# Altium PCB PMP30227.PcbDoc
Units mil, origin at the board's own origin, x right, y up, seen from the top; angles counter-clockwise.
Board outline 3300 x 3700 mil, 2 copper layers (Top Layer, Bottom Layer), stack 62 mil thick; 42 components, 19 nets, 111 pads, 49 vias.
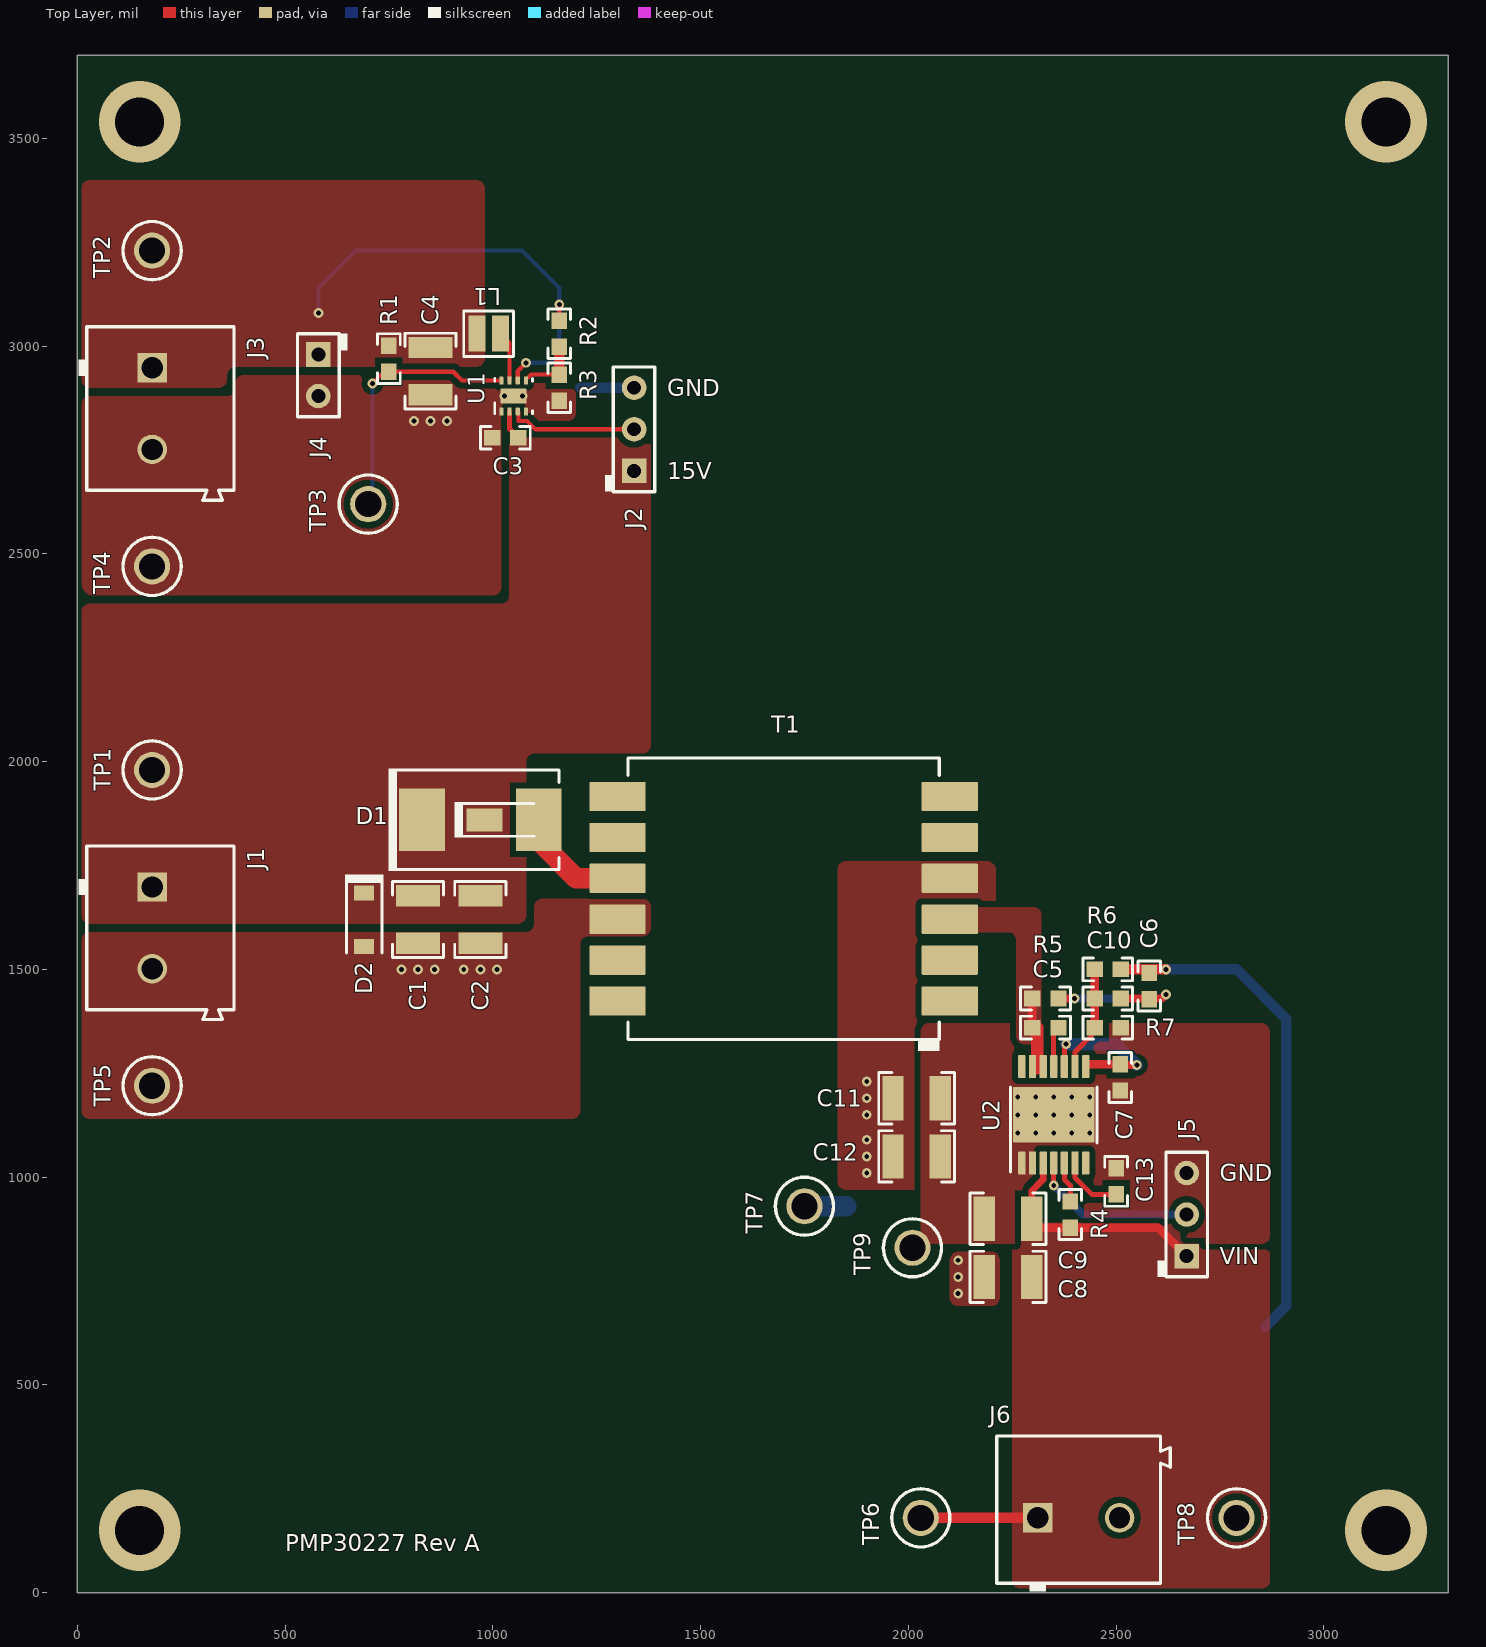
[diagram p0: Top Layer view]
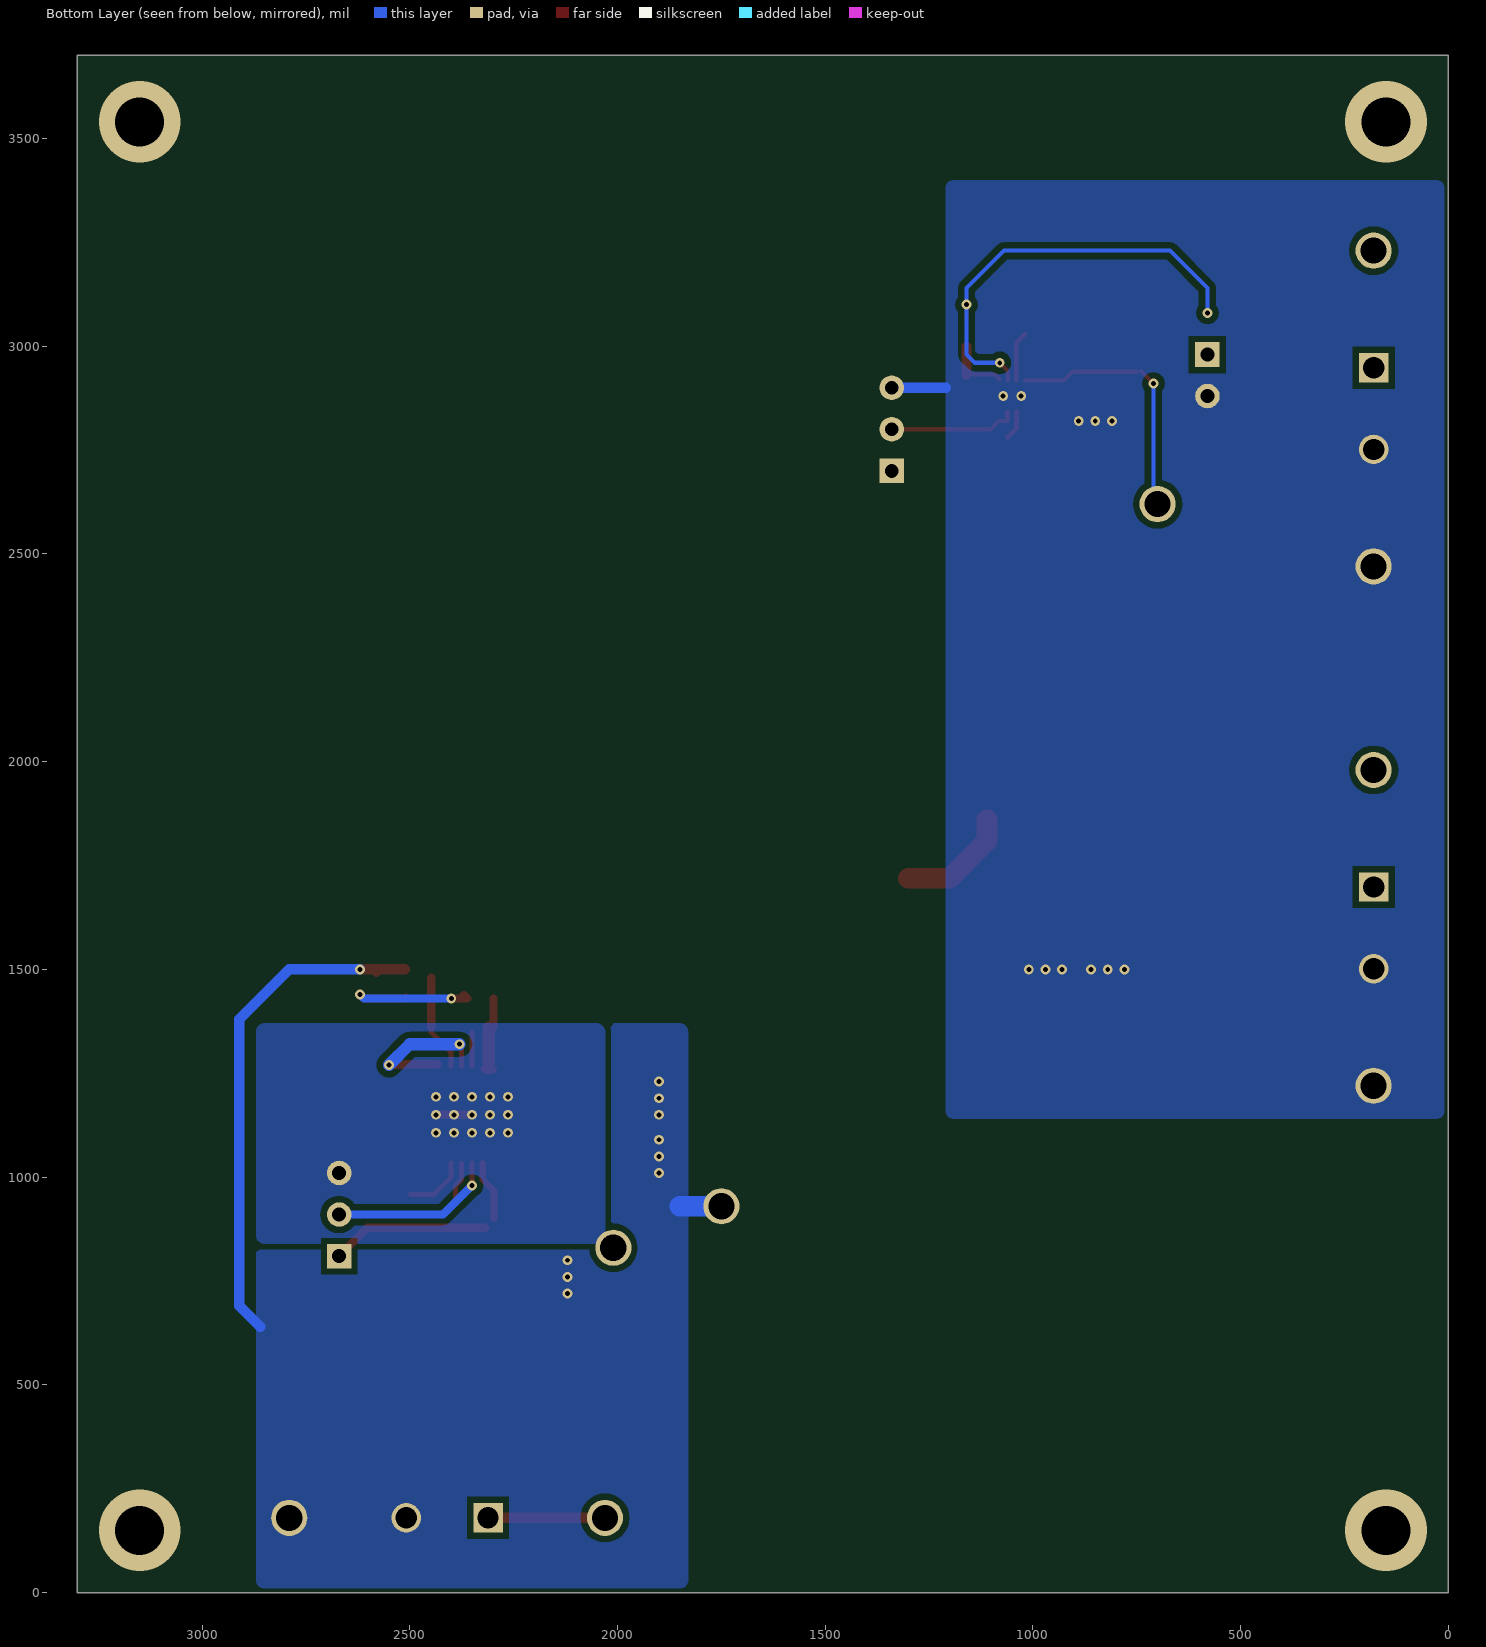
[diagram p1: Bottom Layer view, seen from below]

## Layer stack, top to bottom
Top Solder: solder mask 0.4, Solder Resist, Dk 3.5
Top Layer: signal copper 1.4
Dielectric1: core 59.2, FR-4, Dk 4.8
Bottom Layer: signal copper 1.4
Bottom Solder: solder mask 0.4, Solder Resist, Dk 3.5

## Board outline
0,0 3300,0 3300,3700 0,3700

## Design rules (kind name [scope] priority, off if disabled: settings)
AcuteAngle [All] p1: minimum=4.50000000000000E+0001 checktracksonly=FALSE
AssemblyTestPointUsage [All] p1: valid=2
Clearance Clearance_Keepouts [((IsTrack Or IsArc) And Not InPoly) And IsFree and IsKeepOut vs ((IsTrack Or IsArc) And Not InPoly) And IsFree and IsKeepOut] p1: gap=0
Clearance Clearance_BoardEdge_MountingHoles [OnCopper and InComponentClass('Mounting Holes') vs IsKeepOut] p2: gap=40
Clearance Clearance_BoardEdge_Poly [OnCopper and InPoly vs IsKeepOut] p3: gap=25
Clearance Clearance_BoardEdge [OnCopper and Not InComponentClass('Logo') and not InComponentClass('FiducialMark') and not InRegion(1000,500,4000,800) and Not IsKeepout vs IsKeepOut] p4: gap=75
Clearance Clearance_Poly [InPolygon] p5: gap=15
Clearance [All] p6: gap=7.87
ComponentClearance ComponentClearance_MountingHoles_FiducialMarks [InComponentClass('Mounting Holes') vs InComponentClass('FiducialMark')] p1: gap=50 collisioncheckmode=3 verticalgap=10 showdistances=FALSE
ComponentClearance ComponentClearance_Shunt [InComponentClass('Header') vs InComponentClass('Shunt')] p2: gap=0 collisioncheckmode=3 verticalgap=0 showdistances=FALSE
ComponentClearance ComponentClearance_Logo [InComponentClass('Logo')] p3: gap=50 collisioncheckmode=3 verticalgap=10 showdistances=FALSE
ComponentClearance ComponentClearance_ScrewToNut [(HasFootprint('NY PMS 440 0025 PH')) vs (HasFootprint('Keystone_1902C'))] p4: gap=5 collisioncheckmode=3 verticalgap=10 showdistances=FALSE
ComponentClearance ComponentClearance_MountingHoles [InComponentClass('Mounting Holes')] p5: gap=250 collisioncheckmode=3 verticalgap=100000 showdistances=FALSE
ComponentClearance ComponentClearance_SmallPassives [HasFootprint('0201*') or HasFootprint('0402*') or HasFootprint('0508') or HasFootprint('0603*') or HasFootprint('0612') or HasFootprint('0805*') or HasFootprint('0815*') or HasFootprint('0830*') or HasFootprint('1206*') or HasFootprint('1210*') or HasFootprint('1808*') or HasFootprint('1812*') or HasFootprint('1825*') or HasFootprint('2010*') or HasFootprint('2220*') or HasFootprint('2225*') or HasFootprint('2512*') or HasFootprint('2728*') or HasFootprint('3518*') vs HasFootprint('0201*') or HasFootprint('0402*') or HasFootprint('0508') or HasFootprint('0603*') or HasFootprint('0612') or HasFootprint('0805*') or HasFootprint('0815*') or HasFootprint('0830*') or HasFootprint('1206*') or HasFootprint('1210*') or HasFootprint('1808*') or HasFootprint('1812*') or HasFootprint('1825*') or HasFootprint('2010*') or HasFootprint('2220*') or HasFootprint('2225*') or HasFootprint('2512*') or HasFootprint('2728*') or HasFootprint('3518*')] p6: gap=20 collisioncheckmode=3 verticalgap=10 showdistances=FALSE
ComponentClearance ComponentClearance_THtoSMT [IsThruComponent vs IsSMTComponent] p7: gap=100 collisioncheckmode=3 verticalgap=30 showdistances=FALSE
ComponentClearance ComponentClearance_THtoTH [IsThruComponent vs IsThruComponent] p8: gap=118.11 collisioncheckmode=3 verticalgap=30 showdistances=FALSE
ComponentClearance [All] p9: gap=40 collisioncheckmode=3 verticalgap=10 showdistances=FALSE
DiffPairsRouting [All] p1: maxlimit=100 minlimit=10 mostfreqgap=10 toplayer_minwidth=15 toplayer_maxwidth=15 toplayer_prefwidth=15 bottomlayer_minwidth=15 bottomlayer_maxwidth=15 bottomlayer_prefwidth=15 maxuncoupledlength=1000
FabricationTestPointUsage TestPointUsage [All] p1: valid=2 allowmultiple=FALSE
FabricationTestpoint Testpoint [All] p1: side=3 testpointundercomponent=TRUE minsize=40 maxsize=100 preferedsize=60 minholesize=0 maxholesize=40 preferedholesize=32 testpointgrid=1 allowsidetop=TRUE allowsidebottom=TRUE usegrid=TRUE gridtolerance=0.01
FanoutControl Fanout_LCC [IsLCC] p1: bgadir=Out bgaviamode=Centered fanoutstyle=Auto fanoutdirection=Alternating viagrid=1 // Fanout_LCC (Default Rule)
FanoutControl Fanout_BGA [IsBGA] p2: bgadir=Out bgaviamode=Centered fanoutstyle=Auto fanoutdirection=Alternating viagrid=1 // Fanout_BGA (Default Rule)
FanoutControl Fanout_Default [All] p4: bgadir=Out bgaviamode=Centered fanoutstyle=Auto fanoutdirection=Alternating viagrid=1 // Fanout_Default (Default Rule)
FanoutControl Fanout_Small [(CompPinCount < 5)] p5: bgadir=Out bgaviamode=Centered fanoutstyle=Auto fanoutdirection=OutThenIn viagrid=1 // Fanout_Small (Default Rule)
HoleSize [All] p1: absolutevalues=TRUE maxlimit=251 minlimit=8 maxpercent=80.000 minpercent=20.000
MinimumAnnularRing MinimumAnnularRing_ThermalPadVias [IsVia and InAnyComponent] p1: minimumring=5.91
MinimumAnnularRing [All] p2: minimumring=9
MinimumSolderMaskSliver MinimumSolderMaskSliver_Logo [InComponentClass('Logo') vs InComponentClass('Logo')] p1: minsoldermaskwidth=0.7
MinimumSolderMaskSliver [All] p2: minsoldermaskwidth=3.94
PlaneConnect [All] p1: planeconnectstyle=Relief reliefexpansion=10 reliefentries=4 reliefconductorwidth=10 reliefairgap=10
PolygonConnect [All] p1: connectstyle=Direct reliefconductorwidth=10 reliefentries=4 polygonreliefangle="90 Angle" airgapwidth=10
RoutingVias ThermalPadVias [IsVia and InAnyComponent] p1: holewidth=7.87 width=19.68 viastyle="Through Hole" minholewidth=7.87 minwidth=19.68 maxholewidth=12.99 maxwidth=23.62
RoutingVias [All] p2: holewidth=16 width=34 viastyle="Through Hole" minholewidth=7.87 minwidth=26 maxholewidth=40 maxwidth=65
SilkToBoardRegionClearance [Not ((IsComment or IsDesignator) And (Hide <> 'False')) and not InRegion(1000,500,4000,800)] p1:
SilkToSilkClearance SilkToSilkClearance_Pb-FreeLogo [(HasFootprint('Pb-Free_Overlay_Medium') OR HasFootprint('Pb-Free_Overlay_Small')) vs (HasFootprint('Pb-Free_Overlay_Medium') OR HasFootprint('Pb-Free_Overlay_Small'))] p1: silktosilkclearance=0
SilkToSilkClearance [All] p2: silktosilkclearance=4
SilkToSolderMaskClearance SilkToComonentPadClearance [IsPad and InAnycomponent] p1: minsilkscreentomaskgap=5 clearancetoexposedcopper=TRUE
SilkToSolderMaskClearance "Silk to Solder Mask Opening" [All] p2: minsilkscreentomaskgap=4 clearancetoexposedcopper=FALSE
SolderMaskExpansion [All] p1: expansion=1.97
Width [All] p1: maxlimit=100 minlimit=6 preferedwidth=10 checkconnectedcopper=TRUE
15 further rules are at their usual default settings.

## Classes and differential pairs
component class Header: J2 J4 J5

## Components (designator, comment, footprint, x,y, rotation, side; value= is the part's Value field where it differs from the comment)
C1 "GRM32DR71E106KA12L" 1210_220 820,1620 r270 top
C2 "GRM32DR71E106KA12L" 1210_220 970,1620 r270 top
C3 "GRM188R71E104KA01D" 0603 1030,2780 r180 top
C4 "GRM32ER71A226ME20L" 1210_270 850,2940 r270 top
C5 "GRM188R71C103KA01D" 0603 2330,1360 r0 top
C6 "GRM188R71H103KA01D" 0603 2580,1460 r270 top
C7 "GRM188R71C105KA12D" 0603 2510,1240 r90 top
C8 "GRM32ER71H475KA88L" 1210_270 2240,760 r180 top
C9 "GRM32ER71H475KA88L" 1210_270 2240,900 r180 top
C10 "GRM188R72A102KA01D" 0603 2480,1430 r180 top
C11 "GRM32DR71E106KA12L" 1210_220 2020,1190 r0 top
C12 "GRM32DR71E106KA12L" 1210_220 2020,1050 r0 top
C13 "GRM188R71C104KA01D" 0603 2500,990 r90 top
D1 "DFLS1100-7" PowerDI123 1030,1860 r0 top
D1 "=PartNumber" SMC 970,1860 r0 top
D2 "MMSZ5246B-7-F" SOD-123 690.32,1620 r270 top
J1 "691 101 710 002" Wurth_691101710002 180,1600 r270 top
J2 "800-10-003-10-001000" Mill-Max_800-10-003-10-001000 1340,2800 r90 top
J3 "691 101 710 002" Wurth_691101710002 180,2850 r270 top
J4 "800-10-002-10-001000" Mill-Max_800-10-002-10-001000 580,2930 r270 top
J5 "800-10-003-10-001000" Mill-Max_800-10-003-10-001000 2670,910 r90 top
J6 "691 101 710 002" Wurth_691101710002 2410,180 r0 top
L1 "XPL2010-222MLB" XPL2010 990,3030 r180 top
R1 "CRCW0603100KFKEA" 0603 750,2970 r90 top
R2 "CRCW060368K0JNEA" 0603 1160,3030 r90 top
R3 "CRCW060313K0FKEA" 0603 1160,2900 r90 top
R4 "CRCW0603174KFKEA" 0603 2390,910 r90 top
R5 "CRCW060310K0FKEA" 0603 2330,1430 r0 top
R6 "CRCW0603100KFKEA" 0603 2480,1500 r0 top
R7 "CRCW060335K7FKEA" 0603 2480,1360 r180 top
T1 "WA8417-AL" Coilcraft_WA8417-AL 1700,1670 r180 top
TP1 "5010" Keystone5010 180,1980 r270 top
TP2 "5010" Keystone5010 180,3230 r90 top
TP3 "5012" Keystone5012 700,2620 r90 top
TP4 "5011" Keystone5011 180,2470 r90 top
TP5 "5011" Keystone5011 180,1220 r270 top
TP6 "5010" Keystone5010 2030,180 r90 top
TP7 "5011" Keystone5011 1750,930 r90 top
TP8 "5011" Keystone5011 2790,180 r90 top
TP9 "5010" Keystone5010 2010,830 r90 top
U1 "TPS62170QDSGRQ1" DSG0008A 1050,2880 r90 top
U2 "LM5160QPWPRQ1" PWP0014A_N 2350,1150 r90 top

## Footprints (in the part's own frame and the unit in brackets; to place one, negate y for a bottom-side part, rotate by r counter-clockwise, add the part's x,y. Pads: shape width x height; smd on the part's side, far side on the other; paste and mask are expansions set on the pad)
0603 [mm] "0603 from SM-752 data"
  rect 1x0.95 smd: 1(-0.8,0) 2(0.8,0)
  silkscreen extent -1.52,-0.69 1.52,0.69, body extent -0.87,-0.47 0.87,0.47, height 1
1210_220 [mm] "1210"
  rect 1.3x2.7 smd: 1(-1.45,0) 2(1.45,0)
  silkscreen extent -2.32,-1.57 2.32,1.57, body extent -1.7,-1.35 1.7,1.35, height 2.2
1210_270 [mm] "1210"
  rect 1.3x2.7 smd: 1(-1.45,0) 2(1.45,0)
  silkscreen extent -2.32,-1.57 2.32,1.57, body extent -1.7,-1.35 1.7,1.35, height 2.7
Coilcraft_WA8417-AL [mm] "SMD, 12-Leads, Body 22x17.2mm, Pitch 2.5mm"
  rrect6% 3.43x1.79 smd: 1(-10.155,6.25) 2(-10.155,3.75) 3(-10.155,1.25) 4(-10.155,-1.25) 5(-10.155,-3.75) 6(-10.155,-6.25) 7(10.155,-6.25) 8(10.155,-3.75) 9(10.155,-1.25) 10(10.155,1.25) 11(10.155,3.75) 12(10.155,6.25)
  silkscreen extent -9.52,-8.6 9.52,9.3, body extent -11,-8.6 11,8.6, height 8.64
DSG0008A [mm] "SON, 8-Leads, Body 2x2mm, Pitch 0.5mm, Thermal Pad 1.6x0.9mm, TI Recommended"
  rrect40% 0.5x0.25 smd: 1(-0.95,0.75) 2(-0.95,0.25) 3(-0.95,-0.25) 4(-0.95,-0.75) 5(0.95,-0.75) 6(0.95,-0.25) 7(0.95,0.25) 8(0.95,0.75)
  rrect14% 0.9x0.7 on Top Paste: 9(0,0.45) 9(0,-0.45)
  rrect11% 0.9x1.6 smd paste-0.45: 9(0,0)
  silkscreen extent -1.07,-1.15 1.07,1.15, body extent -1,-1 1,1, height 0.77
Keystone5010 [mil] "Keystone Multipurpose loops"
  round 87 hole 63: 1(0,0)
  silkscreen extent -70,-70 70,70, body extent -63,-63 63,62, height 319
Keystone5011 [mil] "Keystone Multipurpose loops"
  round 87 hole 63: 1(0,0)
  silkscreen extent -70,-70 70,70, body extent -63,-63 63,62, height 319
Keystone5012 [mil] "Keystone Multipurpose loops"
  round 87 hole 63: 1(0,0)
  silkscreen extent -70,-70 70,70, body extent -63,-63 63,62, height 319
Mill-Max_800-10-002-10-001000 [mm] "Mill-Max"
  rect 1.5x1.5 hole 0.85: 1(-1.27,0)
  round 1.5 hole 0.85: 2(1.27,0)
  silkscreen extent -2.54,-1.27 2.54,1.78, body extent -2.54,-1.27 2.54,1.27, height 8.13
Mill-Max_800-10-003-10-001000 [mm] "Mill-Max"
  rect 1.5x1.5 hole 0.85: 1(-2.54,0)
  round 1.5 hole 0.85: 2(0,0) 3(2.54,0)
  silkscreen extent -3.81,-1.27 3.81,1.78, body extent -3.81,-1.27 3.81,1.27, height 8.13
PowerDI123 [mm] "Diodes Inc recommended land pattern, document number DS30628 Rev. 6-2"
  rect 2.2x1.4 smd: 1(-1.275,0)
  rect 0.9x1.4 smd: 2(1.275,0)
  silkscreen extent -3.1,-1.09 1.76,1.09, body extent -2.38,-0.97 1.52,0.96, height 1
PWP0014A_N [mm] "TSOP, 14-Leads, Body 5x4.4mm, Pitch 0.65mm, Thermal Pad 3x3.1 mm, IPC Medium Density"
  rrect22% 1.4x0.45 smd: 1(-2.95,1.95) 2(-2.95,1.3) 3(-2.95,0.65) 4(-2.95,0) 5(-2.95,-0.65) 6(-2.95,-1.3) 7(-2.95,-1.95) 8(2.95,-1.95) 9(2.95,-1.3) 10(2.95,-0.65) 11(2.95,0) 12(2.95,0.65) 13(2.95,1.3) 14(2.95,1.95)
  rrect6% 3.4x5 smd paste-2 mask-2: 15(0,0)
  rrect3% 3.155x3.255 on Top Paste: 15(0,0)
  rrect3% 3.155x3.255 on Top Solder: 15(0,0)
  silkscreen extent -3.47,-2.65 1.7,2.65, body extent -3.21,-2.5 3.21,2.5, height 1
SMC [mil] "Molded Diode, 2-Leads, Body 6.9x5.8mm, IPC Medium Density, based on OnSemi component dimensions and land patterns"
  rect 110x150 smd: 1(-140.49,0) 2(140.49,0)
  silkscreen extent -221,-124 189,124, body extent -156,-116 156,116, height 91
SOD-123 [mm] "On Semi recommended land pattern"
  rect 0.915x1.22 smd: 1(-1.637,0) 2(1.637,0)
  silkscreen extent -2.74,-1.17 2.03,1.17, body extent -1.93,-0.9 1.93,0.9, height 1.35
Wurth_691101710002 [mm] "Terminal Block, 5 mm, 2x1, TH"
  rect 1.8x1.8 hole 1.3: 1(-2.5,0)
  round 1.8 hole 1.3: 2(2.5,0)
  silkscreen extent -5,-4.5 5.6,5, body extent -5.6,-4 5.6,5, height 12.5
XPL2010 [mm] "Coilcraft recommended land pattern Document 646-2 Revised 3/28/11"
  rect 1.04x2.2 smd: 1(-0.725,0) 2(0.725,0)
  silkscreen extent -1.52,-1.4 1.52,1.4, body extent -1.05,-1.1 1.05,1.1, height 1

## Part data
C1 C2 C11 C12: "CAP, CERM, 10 µF, 25 V, +/- 10%, X7R, 1210"
C3: "CAP, CERM, 0.1 µF, 25 V, +/- 10%, X7R, 0603"
C4: "CAP, CERM, 22 µF, 10 V, +/- 10%, X7R, 1210"
C5: "CAP, CERM, 0.01 µF, 16 V, +/- 10%, X7R, 0603"
C6: "CAP, CERM, 0.01 µF, 50 V, +/- 10%, X7R, 0603"
C7: "CAP, CERM, 1 µF, 16 V, +/- 10%, X7R, 0603"
C8 C9: "CAP, CERM, 4.7 µF, 50 V, +/- 10%, X7R, 1210"
C10: "CAP, CERM, 1000 pF, 100 V, +/- 10%, X7R, 0603"
C13: "CAP, CERM, 0.1 µF, 16 V, +/- 10%, X7R, 0603"
D1: "Diode, Schottky, 100 V, 1 A, PowerDI123"
D1: library part VS-30BQ100TRPBF, "Diode, Schottky, 100 V, 3 A, SMC"
D2: "Diode, Zener, 16 V, 500 mW, SOD-123"
J1 J3 J6: "Terminal Block, 5 mm, 2x1, Tin, TH"
J2 J5: "Header, 100mil, 3x1, TH"
J4: "Header, 100mil, 2x1, TH"
L1: "Inductor, Shielded, Composite, 2.2 µH, 1.3 A, 0.16 ohm, SMD"
R1 R6: "RES, 100 k, 1%, 0.1 W, 0603"
R2: "RES, 68 k, 5%, 0.1 W, 0603"
R3: "RES, 13.0 k, 1%, 0.1 W, 0603"
R4: "RES, 174 k, 1%, 0.1 W, 0603"
R5: "RES, 10.0 k, 1%, 0.1 W, 0603"
R7: "RES, 35.7 k, 1%, 0.1 W, 0603"
T1: "Transformer, 47 uH, SMT"
TP1 TP2 TP6 TP9: "Test Point, Multipurpose, Red, TH"
TP3: "Test Point, Multipurpose, White, TH"
TP4 TP5 TP7 TP8: "Test Point, Multipurpose, Black, TH"
U1: "3-17V 0.5A Automotive Step-Down Converter in 2x2 QFN package, DSG0008A (WSON-8)"
U2: "Wide Input 65V, 1.5A Synchronous Buck / Fly-Buck(TM) Converter, PWP0014A (TSSOP-14)"

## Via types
v1: diameter 23.62, hole 11.81, Top Layer to Bottom Layer, 39 vias
v2: diameter 23.62, hole 11.81, Top Layer to Bottom Layer, tented both sides, 6 vias
v3: diameter 196.85, hole 118.11, Top Layer to Bottom Layer, 4 vias

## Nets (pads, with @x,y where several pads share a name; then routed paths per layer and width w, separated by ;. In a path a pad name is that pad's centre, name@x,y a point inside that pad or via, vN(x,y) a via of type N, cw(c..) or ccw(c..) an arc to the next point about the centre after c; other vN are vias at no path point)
15V: C1.1 C2.1 C3.1 D1.1 D2.1 J1.1 J2.1 TP1.1 U1.2 | length 72.9
  Top Layer w10: C3.1@1060,2780 C3.1
  Top Layer w12: U1.2 1040.16,2801.34 C3.1
GND: C6.1 C8.2 C11.1 C12.1 J6.2 R6.2 T1.4 TP7.1 TP8.1 | length 1320.9
  Top Layer w20: C6.1 C6.1@2588.5,1500
  Top Layer w25: R6.2 v1(2620,1500)
  Bottom Layer w25: v1(2620,1500) 2790,1500 2910,1380 2910,690 2860,640
  Bottom Layer w50: TP7.1 1850,930
  other v1: 2120,720 2120,760 2120,800 1900,1010 1900,1050 1900,1090 1900,1150 1900,1190 1900,1230
ISOGND: C1.2 C2.2 C3.2 C4.2 D2.2 J1.2 J2.3 J3.2 J4.2 R3.1 T1.10 TP4.1 TP5.1 U1.1 U1.4 U1.9@1050,2880 | length 131.7
  Bottom Layer w12: v1@1070,2880 v1(1071.65,2880)
  Bottom Layer w25: 1210,2900 J2.3
  other v1: 780,1500 820,1500 860,1500 930,1500 970,1500 1010,1500 810,2820 850,2820 890,2820 1028.35,2880
NetC4_1: C4.1 J3.1 J4.1 L1.2 R1.2 R2.2 TP2.1 U1.6 | length 1052.5
  Top Layer w10: U1.6@1060,2917.56 U1.6 1059.84,2939.84 v1(1080,2960) ; R2.2 v1(1160,3100)
  Bottom Layer w10: v1(580,3080) 580,3140 670,3230 1070,3230 1160,3140 v1(1160,3100) 1160,2980 1140,2960 v1(1080,2960)
NetC5_1: C5.1 R5.1 T1.3 U2.12 U2.13 | length 190.6
  Top Layer w20: R5.1 C5.1 C5.1@2299.96,1358.54 ; U2.13@2299.96,1260.04 U2.12@2319.96,1260.04
  Top Layer w30: 2310,1261.5 C5.1@2310,1360
NetC5_2: C5.2 U2.11 | length 82.4
  Top Layer w12: U2.11 C5.2@2350,1348.5
NetC6_2: C6.2 C10.1 R5.2 | length 389.4
  Top Layer w20: R5.2@2370,1438.5 R5.2 v1(2400,1430) ; C10.1@2510,1431.5 C10.1 2610,1430 v1(2620,1440)
  Bottom Layer w20: v1(2400,1430) 2610,1430 v1(2620,1440)
NetC7_1: C7.1 C9.2 C11.2 C12.2 C13.2 J5.3 R7.1 TP9.1 U2.1 U2.2 U2.15@2350,1150 | length 86.6
  Top Layer w20: v1(2350,1150) v1(2393.31,1150) v2(2436.61,1150)
  other v1: 2306.69,1106.69 2350,1106.69 2393.31,1106.69 2306.69,1150 2306.69,1193.31 2350,1193.31 2393.31,1193.31
  other v2: 2263.39,1106.69 2436.61,1106.69 2263.39,1150 2263.39,1193.31 2436.61,1193.31
NetC7_2: C7.2 U2.8 U2.10 | length 361.6
  Top Layer w12: U2.10 2375.59,1315.59 v1(2380,1320)
  Top Layer w20: U2.8@2433.27,1271.5 C7.2 ; C7.2@2511.5,1270 v1(2550,1270)
  Bottom Layer w29.53: v1(2380,1320) 2500,1320 v1(2550,1270)
NetC8_1: C8.1 C9.1 J5.1 J6.1 R4.1 TP6.1 U2.3 | length 805
  Top Layer w16: C9.1 2297.09,967.09 2324.41,994.41 U2.3
  Top Layer w20: C9.1@2318.58,878.5 R4.1 2601.5,878.5 J5.1
  Top Layer w25: TP6.1 J6.1@2310,180
NetC10_2: C10.2 R6.1 R7.2 U2.9 | length 222
  Top Layer w12: U2.9 2401.18,1301.18 R7.2@2448.5,1348.5
  Top Layer w20: R7.2 C10.2 2448.5,1480
NetC13_1: C13.1 U2.6 | length 150.6
  Top Layer w12: U2.6 2401.18,998.82 2441.5,958.5 C13.1
NetD1_2: D1.2 T1.9 | length 277.6
  Top Layer w50: D1.2@1110.49,1860 1110.49,1809.51 1200.79,1719.21 T1.9
NetJ2_2: J2.2 U1.3 | length 309.9
  Top Layer w10: U1.3 1061.73,2840.71 1061.73,2820.03 1061.88,2819.88 1082.56,2819.88 1102.44,2800 J2.2
NetJ5_2: J5.2 U2.4 | length 402.9
  Top Layer w12: v1(2350,980) U2.4
  Bottom Layer w19.68: v1(2350,980) 2420,910 J5.2
NetL1_1: L1.1 U1.7 | length 121.6
  Top Layer w10: L1.1 1040.16,3008.39 U1.7
NetR1_1: R1.1 TP3.1 U1.8 | length 619.9
  Top Layer w10: v1(710,2910) R1.1@740,2940 ; R1.1 904.65,2938.5 925.75,2917.4 U1.8
  Bottom Layer w10: TP3.1@690,2620 710,2640 v1(710,2910)
NetR2_1: R2.1 R3.2 U1.5 | length 151.8
  Top Layer w10: U1.5@1080,2920 1091.5,2931.5 R3.2
  Top Layer w25: R3.2 R2.1
NetR4_2: R4.2 U2.5 | length 98.3
  Top Layer w12: U2.5 2375.59,994.41 2390,980 R4.2
pads on no net: T1.1 T1.2 T1.5 T1.6 T1.7 T1.8 T1.11 T1.12 U1.9@1032.28,2880 U1.9@1067.72,2880 U2.7 U2.14 U2.15@2350,1150
copper on no net:
  other v3: 150,150 3150,150 150,3540 3150,3540

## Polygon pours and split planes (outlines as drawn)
GND on Top Layer "Top Layer-No Net 8" (solid, remove dead copper, pour order 28): 2100,800 cw(c2120,800) 2120,820 2200,820 cw(c2200,800) 2220,800 2220,710 cw(c2200,710) 2200,690 2120,690 cw(c2120,710) 2100,710
NetC4_1 on Top Layer "Top Layer-No Net" (solid, remove dead copper, pour order 0): 980,3000 980,2980 980,2970 cw(c960,2970) 960,2950 380,2950 ccw(c380,2930) 360,2930 360,2920 cw(c340,2920) 340,2900 30,2900 cw(c30,2920) 10,2920 10,3380 cw(c30,3380) 30,3400 960,3400 cw(c960,3380) 980,3380 980,3000
NetC5_1 on Top Layer "Top Layer-No Net 1" (solid, remove dead copper, pour order 4): 2160,1590 2220,1590 2240,1590 cw(c2240,1570) 2260,1570 2260,1340 ccw(c2280,1340) 2280,1320 2300,1320 ccw(c2300,1340) 2320,1340 2320,1630 ccw(c2300,1630) 2300,1650 2160,1650
ISOGND on Top Layer "Top Layer-No Net 2" (solid, remove dead copper, pour order 6): 10,1470 10,1160 ccw(c30,1160) 30,1140 1190,1140 ccw(c1190,1160) 1210,1160 1210,1560 cw(c1230,1560) 1230,1580 1360,1580 ccw(c1360,1600) 1380,1600 1380,1650 ccw(c1360,1650) 1360,1670 1120,1670 ccw(c1120,1650) 1100,1650 1100,1610 cw(c1080,1610) 1080,1590 30,1590 ccw(c30,1570) 10,1570 10,1470
ISOGND on Top Layer "Top Layer-No Net 3" (solid, remove dead copper, pour order 8): 10,2850 10,2860 cw(c30,2860) 30,2880 360,2880 ccw(c360,2900) 380,2900 380,2910 cw(c400,2910) 400,2930 1180,2930 cw(c1180,2910) 1200,2910 1200,2840 cw(c1180,2840) 1180,2820 1040,2820 ccw(c1040,2800) 1020,2800 1020,2420 cw(c1000,2420) 1000,2400 40,2400 cw(c40,2430) 10,2430
15V on Top Layer "Top Layer-No Net 4" (solid, remove dead copper, pour order 10): 10,1630 ccw(c30,1630) 30,1610 1060,1610 ccw(c1060,1630) 1080,1630 1080,2000 cw(c1100,2000) 1100,2020 1360,2020 ccw(c1360,2040) 1380,2040 1380,2760 ccw(c1360,2760) 1360,2780 1060,2780 ccw(c1060,2760) 1040,2760 1040,2400 cw(c1020,2400) 1020,2380 30,2380 ccw(c30,2360) 10,2360
NetC7_1 on Top Layer "Top Layer-No Net 5" (solid, remove dead copper, pour order 14): 2030,1240 2030,1310 2030,1350 cw(c2050,1350) 2050,1370 2850,1370 cw(c2850,1350) 2870,1350 2870,1110 2870,860 cw(c2850,860) 2850,840 2050,840 cw(c2050,860) 2030,860 2030,1350
GND on Top Layer "Top Layer-No Net 6" (solid, remove dead copper, pour order 18): 2210,990 cw(c2190,990) 2190,970 1850,970 cw(c1850,990) 1830,990 1830,1740 cw(c1850,1740) 1850,1760 2190,1760 cw(c2190,1740) 2210,1740
NetC8_1 on Top Layer "Top Layer-No Net 7" (solid, remove dead copper, pour order 20): 2250,30 ccw(c2270,30) 2270,10 2850,10 ccw(c2850,30) 2870,30 2870,450 2870,870 ccw(c2850,870) 2850,890 2280,890 ccw(c2275,865) 2250,870
ISOGND on Bottom Layer "Bottom Layer-No Net" (solid, remove dead copper, pour order 26): 10,3380 10,1160 ccw(c30,1160) 30,1140 40,1140 1190,1140 ccw(c1190,1160) 1210,1160 1210,3380 ccw(c1190,3380) 1190,3400 30,3400 ccw(c30,3380) 10,3380
NetC7_1 on Bottom Layer "Bottom Layer-No Net 1" (solid, remove dead copper, pour order 16): 2030,1350 2030,1340 2030,860 ccw(c2050,860) 2050,840 2850,840 ccw(c2850,860) 2870,860 2870,1350 ccw(c2850,1350) 2850,1370 2050,1370 ccw(c2050,1350)
GND on Bottom Layer "Bottom Layer-No Net 2" (solid, remove dead copper, pour order 22): 1830,30 ccw(c1850,30) 1850,10 2850,10 ccw(c2850,30) 2870,30 2870,1350 ccw(c2850,1350) 2850,1370 1850,1370 ccw(c1850,1350) 1830,1350

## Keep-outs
Keep-Out Layer:
  lines w10: 4950,-5 ccw(c4950,0) 4955,0 cw(c4950,0) 4950,-5
  text ".Layer_Name" at 577,-858.49 h60

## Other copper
Top Layer:
  text ".Layer_Name" at 577,-858.49 h60
Bottom Layer:
  text ".Layer_Name" at 577,-858.49 h60

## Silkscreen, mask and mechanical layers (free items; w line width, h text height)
Top Overlay:
  text "GND" at 1420,2880 h40
  text "15V" at 1420,2680 h40
  text "GND" at 2750,990 h40
  text "VIN" at 2750,790 h40
  text "PMP30227 Rev A" at 500,100 h40
  text ".Layer_Name" at 577,-858.49 h60
Bottom Overlay:
  text ".Layer_Name" at 577,-858.49 h60
Top Paste:
  text ".Layer_Name" at 577,-858.49 h60
Bottom Paste:
  text ".Layer_Name" at 577,-858.49 h60
Top Solder:
  text "5V" at 280,3210 h40
  text "ISOGND" at 280,2460 h40
  text "15V" at 280,1960 h40
  text "ISOGND" at 280,1210 h40
  text "VIN" at 1980,320 h40
  text "GND" at 2730,320 h40
  text ".Layer_Name" at 577,-858.49 h60
  text ".Layer_Name" at 577,-858.49 h60
Bottom Solder:
  text ".Layer_Name" at 577,-858.49 h60
Drill Guide:
  text ".Layer_Name" at 577,-858.49 h60
M1 Board Outline:
  text ".Layer_Name" at 577,-858.49 h60
M2 Board Dimensions:
  rectangle: 0,-275 125,-150
  rectangle: 125,-400 500,-275
  lines w7: 0,-275 1000,-275 ; 125,-400 125,-150 ; 250,-400 250,-150 ; 500,-400 500,-150 ; 750,-400 750,-150 ; 0,-400 1000,-400 1000,-150 0,-150 0,-400
  text ".Layer_Name" at 577,-858.49 h60
M3 3D STEP Top:
  text ".Layer_Name" at 577,-858.49 h60
M4 3D STEP Bottom:
  text ".Layer_Name" at 577,-858.49 h60
M5 Assembly Top:
  lines w10: -292,-930.17 6308,-930.17 ; -292,-726.83 6310,-726.83 ; -292,-523.5 -292,-1133.5 3713,-1133.5 6310,-1133.5 6310,-523.5 -291.5,-523.5 -291.5,-1133.5 1284,-1133.5 ; 2173,-1133.5 2173,-523.5 ; 3440,-726.83 3440,-523.5 ; 4280,-726.83 4280,-523.5 ; 4902,-1140 4902,-937.17
  text "COMPONENTS MARKED 'DNP' SHOULD NOT BE POPULATED." at 1153.5,-318.5 h60
  text "ASSEMBLY VARIANT:" at 1153,-434 h60
  text ".VariantName" at 2189,-434 h60
  text "PCB VIEWED FROM TOP SIDE" at -228.5,-655.67 h60
  text "BOARD #:" at 2248,-655.67 h60
  text ".PRJ_Number" at 2793.5,-655.67 h60
  text "REV:" at 3638,-655.67 h60
  text ".PCB_Rev" at 3929.5,-655.67 h60
  text "SVN REV:" at 4476,-655.67 h60
  text ".VersionControl_RevNumber" at 4982,-655.67 h60
  text "TID #:" at 2248,-859 h60
  text ".TID" at 2793.5,-859 h60
  text "PLOT NAME =" at -228.5,-1064.34 h60
  text ".plot_File_Name" at 577,-1064.34 h60
  text "GENERATED    :" at 2250,-1064.34 h60
  text ".Print_Date" at 3119.5,-1064.34 h60
  text ".Print_Time" at 3848.5,-1064.34 h60
  text "TEXAS INSTRUMENTS" at 5113,-1064.34 h60
M6 Assembly Bottom:
  lines w10: -292.5,-727.33 6309.5,-727.33 ; -290.5,-930.67 6309.5,-930.67 ; 1115.5,-1140.5 1115.5,-937.67 ; 1737.5,-727.33 1737.5,-524 ; 2577.5,-727.33 2577.5,-524 ; 3844.5,-1134 3844.5,-524 ; 4733.5,-1134 6309,-1134 6309,-524 -292.5,-524 -292.5,-1134 2304.5,-1134 6309.5,-1134 6309.5,-524
  text "COMPONENTS MARKED 'DNP' SHOULD NOT BE POPULATED." at 6102,-318 h60
  text ".VariantName" at 5058,-434 h60
  text "ASSEMBLY VARIANT:" at 6097,-434 h60
  text ".VersionControl_RevNumber" at 1035.5,-656.17 h60
  text "SVN REV:" at 1541.5,-656.17 h60
  text ".PCB_Rev" at 2088,-656.17 h60
  text "REV:" at 2379.5,-656.17 h60
  text ".PRJ_Number" at 3224,-656.17 h60
  text "BOARD #:" at 3769.5,-656.17 h60
  text "PCB VIEWED FROM BOTTOM SIDE" at 6246,-656.17 h60
  text ".TID" at 3224,-859.5 h60
  text "TID #:" at 3769.5,-859.5 h60
  text "TEXAS INSTRUMENTS" at 904.5,-1064.84 h60
  text ".Print_Time" at 2169,-1064.84 h60
  text ".Print_Date" at 2898,-1064.84 h60
  text "GENERATED    :" at 3767.5,-1064.84 h60
  text ".plot_File_Name" at 5440.5,-1064.84 h60
  text "PLOT NAME =" at 6246,-1064.84 h60
M9 Title Sheet:
  drawing of 57 lines, arcs and shapes, not listed
  text "1" at 739.84,8036.5 h70
  text "2" at 3235.5,8036.5 h70
  text "3" at 5724.84,8036.5 h70
  text "4" at 8231.51,8036.5 h70
  text "5" at 10730.5,8036.5 h70
  text "6" at 13235.5,8036.5 h70
  text "A" at -416.5,6893.5 h70
  text "A" at 14383.5,6893.5 h70
  text "B" at -416.5,4513.5 h70
  text "B" at 14383.5,4513.5 h70
  text "C" at -416.5,2138.5 h70
  text "C" at 14383.5,2138.5 h70
  text "PROJECT TITLE:" at 11343.5,277.5 h45
  text ".PRJ_Title" at 11393.5,144.17 h70
  text "DESIGNED FOR:" at 11343.5,-23.5 h45
  text ".PRJ_Customer" at 11393.5,-163.5 h70
  text "D" at -416.5,-231.5 h70
  text "D" at 14383.5,-231.5 h70
  text "FILE NAME:" at 11343.5,-323.5 h45
  text ".PCB_File_Name_No_Path" at 11393.5,-443.5 h70
  text "Texas Instruments (TI) and/or its licensors do not warrant the accuracy or completeness of this specification" at 6374,-605.34 h45
  text "ENGINEER:" at 11343.5,-613.5 h45
  text "LAYOUT BY:" at 12848.5,-613.5 h45
  text "or any information contained therein. TI and/or its licensors do not warrant that this design will meet" at 6329.01,-718 h45
  text ".PRJ_Engineer" at 11393.5,-768.49 h70
  text ".PCB_Layout" at 12899,-768.49 h70
  text "the specifications, will be suitable for your application or fit for any particular purpose, or will operate in" at 6329.01,-830.67 h45
  text ".Layer_Name" at 577,-858.49 h60
  text "ALTIUM DESIGNER VERSION:" at 12848.5,-923.5 h45
  text "an implementation. TI and/or its licensors do not warrant that the design is production worthy. You should" at 6329.01,-943.33 h45
  text "completely validate and test your design implementation to confirm the system functionality for your application." at 6374,-1056 h45
  text ".print_Scale" at 11393.5,-1056.83 h70
  text ".Application_BuildNumber" at 12899,-1056.83 h70
  text "1" at 739.84,-1263.5 h70
  text "2" at 3235.5,-1263.5 h70
  text "3" at 5724.84,-1263.5 h70
  text "4" at 8231.51,-1263.5 h70
  text "5" at 10730.5,-1263.5 h70
  text "6" at 13235.5,-1263.5 h70
M10 Fab Notes:
  text ".Layer_Name" at 577,-858.49 h60
M11 Gerber Information:
  lines w10: -292,-930.17 6308,-930.17 ; -292,-726.83 6310,-726.83 ; -292,-523.5 -292,-1133.5 3713,-1133.5 6310,-1133.5 6310,-523.5 -291.5,-523.5 -291.5,-1133.5 1284,-1133.5 ; 2173,-1133.5 2173,-523.5 ; 3440,-726.83 3440,-523.5 ; 4280,-726.83 4280,-523.5 ; 4902,-1140 4902,-937.17
  text "ALL ARTWORK VIEWED FROM TOP SIDE" at -228.5,-655.67 h60
  text "BOARD #:" at 2248,-655.67 h60
  text ".PRJ_Number" at 2793.5,-655.67 h60
  text "REV:" at 3638,-655.67 h60
  text ".PCB_Rev" at 3929.5,-655.67 h60
  text "SVN REV:" at 4476,-655.67 h60
  text ".VersionControl_RevNumber" at 4982,-655.67 h60
  text "LAYER NAME =" at -228.5,-858.49 h60
  text "TID #:" at 2248,-859 h60
  text ".TID" at 2793.5,-859 h60
  text "PLOT NAME =" at -228.5,-1064.34 h60
  text ".plot_File_Name" at 577,-1064.34 h60
  text "GENERATED    :" at 2250,-1064.34 h60
  text ".Print_Date" at 3119.5,-1064.34 h60
  text ".Print_Time" at 3848.5,-1064.34 h60
  text "TEXAS INSTRUMENTS" at 5113,-1064.34 h60
M12 Stackup:
  text ".Layer_Name" at 577,-858.49 h60
M13 Component Bodies Top:
  text ".Layer_Name" at 577,-858.49 h60
M14 Component Bodies Bottom:
  text ".Layer_Name" at 577,-858.49 h60
M15 Courtyards Top:
  text ".Layer_Name" at 577,-858.49 h60
M16 Courtyards Bottom:
  text ".Layer_Name" at 577,-858.49 h60
Drill Drawing:
  text ".Layer_Name" at 577,-858.49 h60

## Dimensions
0,-400 to 1000,-400 on M2 Board Dimensions
0,0 to 3300,0 on M2 Board Dimensions
0,0 to 0,3700 on M2 Board Dimensions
